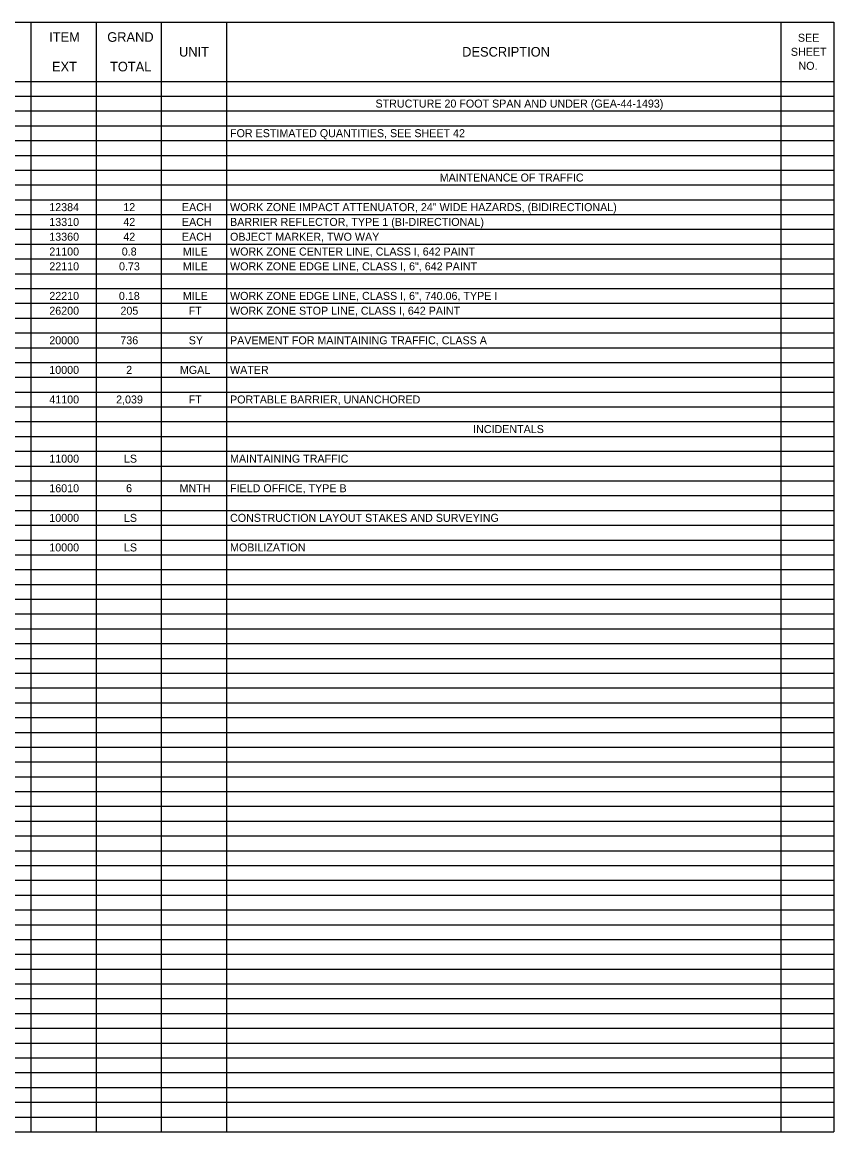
# Model space of a CAD drawing. Extents: x -50.3 to 36.4, y 0 to 22.5.
# Drawn here: x -35.16 to -19.8, y 1.54 to 22.54 of the extents above; entities that cross this region are included whole.
import ezdxf

# ---------------------------------------------------------------- set-up
doc = ezdxf.new("R2010")
doc.units = 0
doc.layers.add('SH_Text', color=7, linetype='Continuous')

msp = doc.modelspace()

# ---------------------------------------------------------------- linework, layer by layer
at = {"layer": 'SH_Text'}
for p, q in [((-50.299, 22.544), (-19.796, 22.544)), ((-34.998, 22.544), (-34.998, 1.544)), ((-33.763, 22.544), (-33.763, 1.544)), ((-32.528, 22.544), (-32.528, 1.544)), ((-31.292, 22.544), (-31.292, 1.544)), ((-20.801, 22.544), (-20.801, 1.544)), ((-19.796, 22.544), (-19.796, 1.544)), ((-50.299, 21.424), (-19.796, 21.424)), ((-50.299, 21.144), (-19.796, 21.144)), ((-50.299, 20.864), (-19.796, 20.864)), ((-50.299, 20.584), (-19.796, 20.584)), ((-50.299, 20.304), (-19.796, 20.304)), ((-50.299, 20.024), (-19.796, 20.024)), ((-50.299, 19.744), (-19.796, 19.744)), ((-50.299, 19.464), (-19.796, 19.464)), ((-50.299, 19.184), (-19.796, 19.184)), ((-50.299, 18.904), (-19.796, 18.904)), ((-50.299, 18.624), (-19.796, 18.624)), ((-50.299, 18.344), (-19.796, 18.344)), ((-50.299, 18.064), (-19.796, 18.064)), ((-50.299, 17.784), (-19.796, 17.784)), ((-50.299, 17.504), (-19.796, 17.504)), ((-50.299, 17.224), (-19.796, 17.224)), ((-50.299, 16.944), (-19.796, 16.944)), ((-50.299, 16.664), (-19.796, 16.664)), ((-50.299, 16.384), (-19.796, 16.384)), ((-50.299, 16.104), (-19.796, 16.104)), ((-50.299, 15.824), (-19.796, 15.824)), ((-50.299, 15.544), (-19.796, 15.544)), ((-50.299, 15.264), (-19.796, 15.264)), ((-50.299, 14.984), (-19.796, 14.984)), ((-50.299, 14.704), (-19.796, 14.704)), ((-50.299, 14.424), (-19.796, 14.424)), ((-50.299, 14.144), (-19.796, 14.144)), ((-50.299, 13.864), (-19.796, 13.864)), ((-50.299, 13.584), (-19.796, 13.584)), ((-50.299, 13.304), (-19.796, 13.304)), ((-50.299, 13.024), (-19.796, 13.024)), ((-50.299, 12.744), (-19.796, 12.744)), ((-50.299, 12.464), (-19.796, 12.464)), ((-50.299, 12.184), (-19.796, 12.184)), ((-50.299, 11.904), (-19.796, 11.904)), ((-50.299, 11.624), (-19.796, 11.624)), ((-50.299, 11.344), (-19.796, 11.344)), ((-50.299, 11.064), (-19.796, 11.064)), ((-50.299, 10.784), (-19.796, 10.784)), ((-50.299, 10.504), (-19.796, 10.504)), ((-50.299, 10.224), (-19.796, 10.224)), ((-50.299, 9.944), (-19.796, 9.944)), ((-50.299, 9.664), (-19.796, 9.664)), ((-50.299, 9.384), (-19.796, 9.384)), ((-50.299, 9.104), (-19.796, 9.104)), ((-50.299, 8.824), (-19.796, 8.824)), ((-50.299, 8.544), (-19.796, 8.544)), ((-50.299, 8.264), (-19.796, 8.264)), ((-50.299, 7.984), (-19.796, 7.984)), ((-50.299, 7.704), (-19.796, 7.704)), ((-50.299, 7.424), (-19.796, 7.424)), ((-50.299, 7.144), (-19.796, 7.144)), ((-50.299, 6.864), (-19.796, 6.864)), ((-50.299, 6.584), (-19.796, 6.584)), ((-50.299, 6.304), (-19.796, 6.304)), ((-50.299, 6.024), (-19.796, 6.024)), ((-50.299, 5.744), (-19.796, 5.744)), ((-50.299, 5.464), (-19.796, 5.464)), ((-50.299, 5.184), (-19.796, 5.184)), ((-50.299, 4.904), (-19.796, 4.904)), ((-50.299, 4.624), (-19.796, 4.624)), ((-50.299, 4.344), (-19.796, 4.344)), ((-50.299, 4.064), (-19.796, 4.064)), ((-50.299, 3.784), (-19.796, 3.784)), ((-50.299, 3.504), (-19.796, 3.504)), ((-50.299, 3.224), (-19.796, 3.224)), ((-50.299, 2.944), (-19.796, 2.944)), ((-50.299, 2.664), (-19.796, 2.664)), ((-50.299, 2.384), (-19.796, 2.384)), ((-50.299, 2.104), (-19.796, 2.104)), ((-50.299, 1.824), (-19.796, 1.824)), ((-50.299, 1.544), (-19.796, 1.544))]:
    msp.add_line(p, q, dxfattribs=at)

# ---------------------------------------------------------------- texts
for s, height, p in [('ITEM', 0.1818, (-34.652, 22.173)), ('GRAND', 0.1818, (-33.552, 22.173)), ('SEE ', 0.1515, (-20.476, 22.174)), ('UNIT', 0.1818, (-32.193, 21.893)), ('DESCRIPTION', 0.18184, (-26.832, 21.893)), ('SHEET ', 0.1515, (-20.609, 21.908)), ('EXT', 0.1818, (-34.598, 21.613)), ('TOTAL', 0.1818, (-33.5, 21.613)), ('NO.', 0.1515, (-20.465, 21.643)), ('STRUCTURE 20 FOOT SPAN AND UNDER (GEA-44-1493)', 0.15153, (-28.473, 20.928)), ('FOR ESTIMATED QUANTITIES, SEE SHEET 42', 0.15153, (-31.227, 20.368)), ('MAINTENANCE OF TRAFFIC', 0.15153, (-27.257, 19.528)), ('12384', 0.1515, (-34.65, 18.968)), ('12', 0.1515, (-33.248, 18.968)), ('EACH', 0.1515, (-32.138, 18.968)), ('WORK ZONE IMPACT ATTENUATOR, 24" WIDE HAZARDS, (BIDIRECTIONAL)', 0.15153, (-31.227, 18.968)), ('13310', 0.1515, (-34.649, 18.688)), ('42', 0.1515, (-33.248, 18.688)), ('EACH', 0.1515, (-32.138, 18.688)), ('BARRIER REFLECTOR, TYPE 1 (BI-DIRECTIONAL)', 0.15153, (-31.227, 18.688)), ('13360', 0.1515, (-34.649, 18.408)), ('42', 0.1515, (-33.248, 18.408)), ('EACH', 0.1515, (-32.138, 18.408)), ('OBJECT MARKER, TWO WAY', 0.15153, (-31.227, 18.408)), ('21100', 0.1515, (-34.649, 18.128)), ('0.8', 0.1515, (-33.277, 18.128)), ('MILE', 0.1515, (-32.121, 18.128)), ('WORK ZONE CENTER LINE, CLASS I, 642 PAINT', 0.15153, (-31.227, 18.128)), ('22110', 0.1515, (-34.649, 17.848)), ('0.73', 0.1515, (-33.329, 17.848)), ('MILE', 0.1515, (-32.121, 17.848)), ('WORK ZONE EDGE LINE, CLASS I, 6", 642 PAINT', 0.15153, (-31.227, 17.848)), ('22210', 0.1515, (-34.649, 17.288)), ('0.18', 0.1515, (-33.331, 17.288)), ('MILE', 0.1515, (-32.121, 17.288)), ('WORK ZONE EDGE LINE, CLASS I, 6", 740.06, TYPE I', 0.15153, (-31.227, 17.288)), ('26200', 0.1515, (-34.649, 17.008)), ('205', 0.1515, (-33.302, 17.008)), ('FT', 0.1515, (-32.011, 17.008)), ('WORK ZONE STOP LINE, CLASS I, 642 PAINT', 0.15153, (-31.227, 17.008)), ('20000', 0.1515, (-34.649, 16.448)), ('736', 0.1515, (-33.304, 16.448)), ('SY', 0.1515, (-32.009, 16.448)), ('PAVEMENT FOR MAINTAINING TRAFFIC, CLASS A', 0.15153, (-31.227, 16.448)), ('10000', 0.1515, (-34.649, 15.888)), ('2', 0.152, (-33.194, 15.888)), ('MGAL', 0.1515, (-32.176, 15.888)), ('WATER', 0.1515, (-31.227, 15.888)), ('41100', 0.1515, (-34.649, 15.328)), ('2,039', 0.1515, (-33.384, 15.328)), ('FT', 0.1515, (-32.011, 15.328)), ('PORTABLE BARRIER, UNANCHORED', 0.15153, (-31.227, 15.328)), ('INCIDENTALS', 0.15153, (-26.625, 14.768)), ('11000', 0.1515, (-34.649, 14.208)), ('LS', 0.1515, (-33.236, 14.208)), ('MAINTAINING TRAFFIC', 0.15153, (-31.227, 14.208)), ('16010', 0.1515, (-34.649, 13.648)), ('6', 0.152, (-33.196, 13.648)), ('MNTH', 0.1515, (-32.182, 13.648)), ('FIELD OFFICE, TYPE B', 0.15153, (-31.227, 13.648)), ('10000', 0.1515, (-34.649, 13.088)), ('LS', 0.1515, (-33.236, 13.088)), ('CONSTRUCTION LAYOUT STAKES AND SURVEYING', 0.15153, (-31.227, 13.088)), ('10000', 0.1515, (-34.649, 12.528)), ('LS', 0.1515, (-33.236, 12.528)), ('MOBILIZATION', 0.15153, (-31.227, 12.528))]:
    msp.add_text(s, height=height, dxfattribs=at).set_placement(p)

doc.saveas('drawing.dxf')
